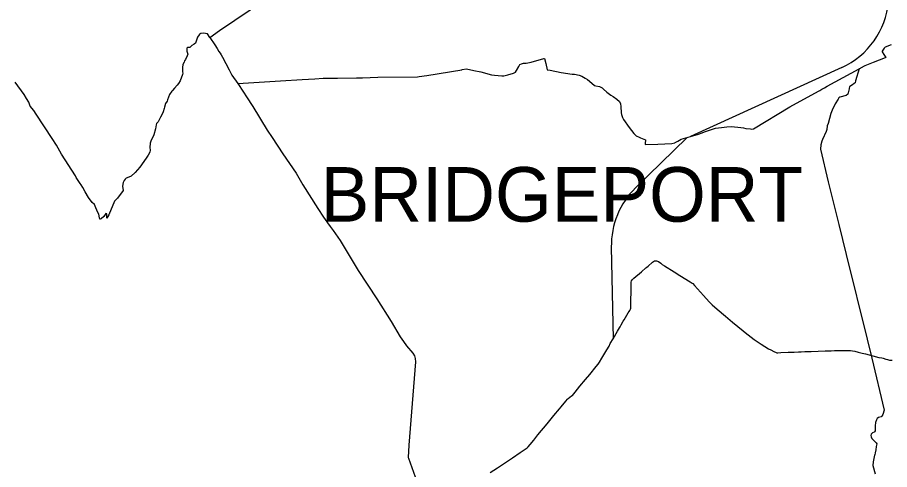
# Model space of a CAD drawing. Extents: x 0 to 2603, y -226 to 830.
# Drawn here: x 98.95 to 120.53, y 503.71 to 514.89 of the extents above; entities that cross this region are included whole.
import ezdxf

# ---------------------------------------------------------------- set-up
doc = ezdxf.new("R2010")
doc.units = 0
for name, color, linetype in [('CT_TSH_Map_Town_Limits', 7, 'Continuous'), ('CT_TSH_Map_Town_Text', 7, 'Continuous'), ('CT_TSH_Map_US_and_State_Routes', 7, 'Continuous')]:
    doc.layers.add(name, color=color, linetype=linetype)

msp = doc.modelspace()

# ---------------------------------------------------------------- linework, layer by layer
at = {"layer": 'CT_TSH_Map_Town_Limits'}
for points in [[(103.709, 514.393), (103.955, 514.563), (105.822, 515.834)], [(103.709, 514.393), (103.654, 514.486), (103.554, 514.497), (103.492, 514.488), (103.469, 514.477), (103.452, 514.466), (103.446, 514.456), (103.404, 514.401), (103.394, 514.352), (103.361, 514.255), (103.322, 514.226), (103.264, 514.193), (103.216, 514.148), (103.206, 514.142), (103.166, 514.142), (103.146, 514.127), (103.14, 514.092), (103.146, 514.051), (103.167, 513.982), (103.155, 513.937), (103.108, 513.846), (103.084, 513.812), (103.074, 513.783), (103.046, 513.726), (103.035, 513.648), (103.038, 513.547), (103.042, 513.508), (103.036, 513.478), (102.981, 513.322), (102.938, 513.255), (102.901, 513.217), (102.84, 513.14), (102.787, 513.085), (102.77, 513.068), (102.716, 512.984), (102.691, 512.921), (102.669, 512.851), (102.653, 512.817), (102.616, 512.763), (102.587, 512.673), (102.581, 512.636), (102.556, 512.553), (102.521, 512.48), (102.494, 512.42), (102.434, 512.309), (102.396, 512.267), (102.383, 512.232), (102.372, 512.136), (102.325, 511.987), (102.252, 511.833), (102.238, 511.781), (102.226, 511.672), (102.235, 511.605), (102.226, 511.56), (102.185, 511.484), (102.136, 511.411), (101.977, 511.186), (101.926, 511.12), (101.864, 511.055), (101.766, 510.965), (101.748, 510.954), (101.642, 510.911), (101.615, 510.891), (101.59, 510.856), (101.569, 510.811), (101.553, 510.72), (101.571, 510.61), (101.426, 510.419), (101.355, 510.344), (101.211, 510.012), (101.163, 509.923), (101.16, 510.031), (101.156, 510.037), (101.142, 510.042), (101.088, 509.966), (101.024, 509.907), (101.002, 509.899), (100.991, 509.904), (100.981, 509.935), (100.965, 510.026), (100.935, 510.086), (100.879, 510.222), (100.856, 510.261), (100.803, 510.311), (100.714, 510.439), (100.629, 510.576), (100.568, 510.688), (100.525, 510.746), (100.506, 510.784), (100.406, 510.934), (100.388, 510.969), (100.045, 511.512), (99.918, 511.731), (99.808, 511.898), (99.414, 512.5), (99.354, 512.587), (99.271, 512.691), (99.233, 512.794), (99.177, 512.888), (99.115, 512.987), (98.893, 513.291)], [(103.709, 514.393), (103.833, 514.208), (103.894, 514.119), (103.935, 514.049), (103.968, 514.005), (103.99, 513.963), (104.027, 513.906), (104.189, 513.592), (104.255, 513.465), (104.404, 513.253)], [(120.572, 514.209), (120.424, 514.151), (120.397, 514.131), (120.344, 514.052), (120.344, 514.036), (120.393, 513.974), (120.436, 513.902), (120.418, 513.894), (120.129, 513.774), (119.921, 513.691), (119.81, 513.636), (119.802, 513.63), (119.776, 513.621)], [(104.404, 513.253), (105.457, 513.323), (105.998, 513.355), (106.308, 513.373), (106.519, 513.385), (106.869, 513.387), (107.343, 513.397), (107.403, 513.398), (107.49, 513.399), (107.867, 513.409), (108.852, 513.423), (108.891, 513.425), (109.084, 513.45), (109.948, 513.594), (109.959, 513.601), (110.065, 513.62), (110.242, 513.579), (110.417, 513.54), (110.682, 513.473), (110.754, 513.458), (110.937, 513.447), (110.983, 513.449), (111.088, 513.471), (111.23, 513.514), (111.272, 513.539), (111.302, 513.573), (111.359, 513.672), (111.386, 513.722), (111.424, 513.745), (111.474, 513.756), (111.542, 513.758), (111.662, 513.779), (111.974, 513.876), (111.996, 513.876), (112.028, 513.752), (112.057, 513.593), (112.135, 513.583), (112.404, 513.529), (112.678, 513.487), (112.732, 513.486), (112.848, 513.459), (112.917, 513.433), (113.002, 513.384), (113.053, 513.358), (113.164, 513.266), (113.233, 513.206), (113.266, 513.198), (113.356, 513.185), (113.419, 513.149), (113.456, 513.117), (113.537, 513.039), (113.631, 512.967), (113.69, 512.932), (113.781, 512.867), (113.848, 512.808), (113.873, 512.756), (113.88, 512.685), (113.889, 512.532), (113.896, 512.487), (113.923, 512.412), (113.946, 512.366), (114.085, 512.168), (114.202, 512.023), (114.262, 511.961), (114.335, 511.926), (114.368, 511.914), (114.49, 511.861), (114.484, 511.769), (114.485, 511.75), (114.796, 511.752), (115.144, 511.771), (115.214, 511.785), (115.224, 511.796), (115.291, 511.828), (115.378, 511.877), (115.723, 511.977), (115.802, 511.999), (115.939, 512.05), (115.952, 512.058), (116.228, 512.15), (116.369, 512.167), (116.502, 512.188), (116.622, 512.192), (116.854, 512.169), (116.917, 512.161), (116.978, 512.144), (117.092, 512.136), (117.124, 512.124), (117.161, 512.135), (118.063, 512.675), (118.503, 512.921), (118.791, 513.077), (118.808, 513.08), (118.852, 513.113), (118.924, 513.15), (118.99, 513.19), (119.776, 513.621)], [(119.776, 513.621), (119.692, 513.321), (119.677, 513.276), (119.657, 513.256), (119.612, 513.221), (119.546, 513.179), (119.536, 513.17), (119.528, 513.143), (119.528, 513.121), (119.509, 513.021), (119.499, 512.99), (119.459, 512.957), (119.303, 512.92), (119.279, 512.902), (119.255, 512.869), (119.188, 512.756), (119.107, 512.595), (119.075, 512.516), (119.012, 512.264), (118.991, 512.208), (118.981, 512.117), (118.965, 512.067), (118.868, 511.873), (118.852, 511.828), (118.832, 511.735), (118.821, 511.63), (119.014, 510.827), (119.275, 509.766), (119.457, 509.028), (119.975, 506.933), (120.091, 506.466), (120.394, 505.182), (120.364, 505.068), (120.338, 505.029), (120.319, 505.013), (120.256, 504.995), (120.221, 504.971), (120.208, 504.937), (120.184, 504.878), (120.173, 504.788), (120.171, 504.67), (120.159, 504.64), (120.15, 504.634), (120.111, 504.619), (120.077, 504.587), (120.066, 504.555), (120.074, 504.52), (120.094, 504.478), (120.168, 504.402), (120.202, 504.372), (120.214, 504.343), (120.21, 504.317), (120.201, 504.281), (120.19, 504.202), (120.172, 504.123), (120.165, 504.076), (120.16, 504.067), (120.135, 503.944), (120.126, 503.905), (120.119, 503.807), (120.176, 503.601)], [(104.404, 513.253), (104.543, 513.038), (104.622, 512.924), (104.776, 512.688), (105.13, 512.099), (105.252, 511.918), (105.52, 511.52), (105.851, 511.037), (106.012, 510.753), (106.383, 510.164), (106.526, 509.954), (106.61, 509.835), (106.623, 509.812), (106.693, 509.719), (106.761, 509.622), (106.936, 509.373), (107.382, 508.635), (107.847, 507.935), (108.202, 507.369), (108.425, 506.989), (108.507, 506.874), (108.581, 506.771), (108.737, 506.589), (108.774, 506.522), (108.795, 506.453), (108.802, 506.377), (108.637, 504.31), (108.62, 504.008), (108.624, 503.995), (108.838, 503.418)]]:
    msp.add_lwpolyline(points, dxfattribs=at)
at = {"layer": 'CT_TSH_Map_US_and_State_Routes'}
for p, q in [((119.348, 513.652), (115.602, 511.942)), ((115.515, 511.916), (114.247, 510.676)), ((113.646, 509.21), (113.688, 506.946)), ((114.555, 508.741), (114.666, 508.836)), ((114.528, 508.716), (114.555, 508.741)), ((114.143, 508.373), (114.158, 508.4)), ((115.344, 508.51), (115.595, 508.352)), ((114.127, 507.802), (114.135, 508.204)), ((115.928, 508.014), (116.071, 507.857)), ((116.269, 507.675), (116.472, 507.502)), ((113.889, 507.286), (113.943, 507.378)), ((113.943, 507.378), (113.963, 507.41)), ((116.472, 507.502), (116.643, 507.357)), ((116.643, 507.357), (116.912, 507.14)), ((113.864, 507.242), (113.889, 507.286)), ((116.912, 507.14), (116.959, 507.101)), ((116.959, 507.101), (117.184, 506.93)), ((113.617, 506.825), (113.688, 506.946)), ((117.184, 506.93), (117.351, 506.81)), ((113.434, 506.504), (113.535, 506.668)), ((113.35, 506.366), (113.411, 506.466)), ((113.411, 506.466), (113.434, 506.504)), ((117.77, 506.597), (117.844, 506.605)), ((117.844, 506.605), (118.02, 506.61)), ((118.02, 506.61), (118.116, 506.614)), ((118.116, 506.614), (118.167, 506.616)), ((118.167, 506.616), (118.276, 506.62)), ((118.276, 506.62), (118.344, 506.622)), ((118.344, 506.622), (118.436, 506.626)), ((118.436, 506.626), (118.502, 506.628)), ((118.502, 506.628), (118.594, 506.631)), ((118.594, 506.631), (118.935, 506.644)), ((118.935, 506.644), (119.086, 506.649)), ((119.086, 506.649), (119.167, 506.651)), ((119.167, 506.651), (119.341, 506.655)), ((119.673, 506.634), (119.755, 506.614)), ((119.755, 506.614), (119.852, 506.59)), ((119.852, 506.59), (119.932, 506.57)), ((119.932, 506.57), (120.114, 506.525)), ((120.114, 506.525), (120.269, 506.485)), ((113.111, 506.064), (113.275, 506.261)), ((113.009, 505.94), (113.111, 506.064)), ((112.871, 505.773), (113.009, 505.94)), ((112.752, 505.627), (112.871, 505.773)), ((112.406, 505.264), (112.517, 505.398)), ((111.827, 504.565), (112.056, 504.842)), ((111.725, 504.441), (111.827, 504.565)), ((111.2, 504.003), (111.387, 504.13)), ((110.827, 503.755), (111.001, 503.871)), ((111.001, 503.871), (111.2, 504.003)), ((110.647, 503.636), (110.827, 503.755))]:
    msp.add_line(p, q, dxfattribs=at)
for points in [[(114.666, 508.836), (114.689, 508.855), (114.713, 508.868), (114.737, 508.873), (114.765, 508.873), (114.792, 508.865), (114.814, 508.856)], [(114.814, 508.856), (114.872, 508.81), (114.907, 508.784), (114.962, 508.748)], [(114.39, 508.6), (114.504, 508.698), (114.528, 508.716)], [(114.962, 508.748), (115.202, 508.599), (115.344, 508.51)], [(114.158, 508.4), (114.204, 508.442), (114.39, 508.6)], [(114.135, 508.204), (114.137, 508.333), (114.136, 508.343), (114.143, 508.373)], [(115.595, 508.352), (115.644, 508.321), (115.66, 508.308), (115.706, 508.26), (115.928, 508.014)], [(113.963, 507.41), (114.067, 507.589), (114.087, 507.62), (114.104, 507.642), (114.117, 507.672), (114.126, 507.703), (114.127, 507.802)], [(116.071, 507.857), (116.139, 507.784), (116.269, 507.675)], [(113.688, 506.946), (113.797, 507.133), (113.847, 507.216), (113.864, 507.242)], [(113.535, 506.668), (113.591, 506.764), (113.617, 506.825)], [(117.351, 506.81), (117.445, 506.75), (117.536, 506.699), (117.595, 506.667), (117.671, 506.631), (117.725, 506.605), (117.744, 506.597), (117.77, 506.597)], [(119.341, 506.655), (119.475, 506.658), (119.521, 506.656)], [(119.521, 506.656), (119.568, 506.653), (119.617, 506.647), (119.673, 506.634)], [(120.269, 506.485), (120.34, 506.469), (120.37, 506.464), (120.438, 506.441)], [(113.275, 506.261), (113.318, 506.315), (113.35, 506.366)], [(120.438, 506.441), (120.483, 506.428), (120.532, 506.419), (120.592, 506.413)], [(112.623, 505.501), (112.665, 505.53), (112.683, 505.545), (112.752, 505.627)], [(112.517, 505.398), (112.559, 505.448), (112.575, 505.465), (112.623, 505.501)], [(112.056, 504.842), (112.228, 505.049), (112.362, 505.209), (112.406, 505.264)], [(111.587, 504.272), (111.635, 504.333), (111.725, 504.441)], [(111.387, 504.13), (111.543, 504.235), (111.567, 504.25), (111.587, 504.272)]]:
    msp.add_lwpolyline(points, dxfattribs=at)
for centre, start, end in [((118.517, 515.471), 294.548, 354.4991), ((115.646, 509.247), 134.3675, 181.0621)]:
    msp.add_arc(centre, 2, start, end, dxfattribs=at)

# ---------------------------------------------------------------- texts
at = {"layer": 'CT_TSH_Map_Town_Text'}
msp.add_text('BRIDGEPORT', height=1.35, dxfattribs=at).set_placement((106.455, 509.839))

doc.saveas('drawing.dxf')
